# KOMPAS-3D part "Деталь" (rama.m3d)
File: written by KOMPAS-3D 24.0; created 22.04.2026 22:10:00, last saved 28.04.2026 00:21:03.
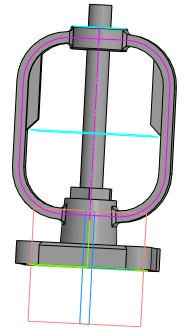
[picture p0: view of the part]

Document properties: Автор: mrdid; Полное имя файла: C:\Работа\ГОТОВЫЕ ИСХОДНИКИ\VSO2130M-F-S Клапан запорный сальниковый DN.ru Ду15-100 Ру40\исходные материалы\DN20\rama.m3d

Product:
- Part/product: Деталь
    Масса: 0.512593

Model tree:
1. Эскиз:2  (with: Ребро.Элемент выдавливания:14)
2. Элемент выдавливания:1
     Расстояние 1 = 10
3. Эскиз:3  (with: Грань.Элемент выдавливания:1, Ребро.Элемент выдавливания:1)
4. Элемент выдавливания:2
     Расстояние 2 = 10
5. Эскиз:4  (with: Грань.Элемент выдавливания:1)
6. Элемент выдавливания:3
     Угол 1 = -3
7. Эскиз:5  (with: Грань.Элемент выдавливания:3, Ребро.Элемент выдавливания:3)
8. Элемент выдавливания:4
9. Эскиз:23  (with: Грань.Элемент выдавливания:4, Ребро.Элемент выдавливания:4)
10. Элемент выдавливания:21  (labels: Деталь2; Грань.Твердое тело1)
     Расстояние 1 = 80.9875
11. Эскиз:7  (with: Грань.Элемент выдавливания:4, Ребро.Элемент выдавливания:3)
12. Элемент выдавливания:6  (with: Грань.Элемент выдавливания:3)
     Расстояние 2 = 5
13. Смещенная плоскость:4  (labels: Деталь2; Грань.Твердое тело1)
     Расстояние = 10
14. Эскиз:24  (with: Ребро.Элемент выдавливания:3)
15. Элемент выдавливания:22
     Расстояние 2 = 10
16. Эскиз:25  (with: Ребро.Элемент выдавливания:3)
17. Эскиз:26  (with: Ребро.Элемент выдавливания:3)
18. Элемент по траектории:1
     Длина траектории = 251.639
19. Скругление:8  (with: Ребро.Элемент по траектории:1)
     Радиус = 2
20. Скругление:9  (with: Ребро.Элемент по траектории:1)
     Радиус = 2
21. Смещенная плоскость:5  (with: Грань.Элемент выдавливания:1)
22. Эскиз:27  (with: Вершина.Элемент по траектории:1)
23. Элемент выдавливания:23  (with: Грань.Элемент выдавливания:22)
     Расстояние 1 = 33.7375; Смещение 1 = -3
24. Скругление:1  (with: Ребро.Элемент выдавливания:1)
     Радиус = 1.5
25. Скругление:10  (with: Ребро.Элемент выдавливания:22)
     Радиус = 0.5
26. Фаска:1  (with: Ребро.Элемент выдавливания:23)
     Угол = 45; Длина 1 = 5; Длина 2 = 5
27. Массив по концентрической сетке:1  (with: Элемент выдавливания:2, Эскиз:3)  (labels: Клапан запорный DN.ru Ду20 Ру40)  (4 pattern instances)
     Шаг 2 = 360

Expressions: DN/2; DN/4; H/4
Referenced files in C:\Работа\ГОТОВЫЕ ИСХОДНИКИ\VSO2130M-F-S Клапан запорный сальниковый DN.ru Ду15-100 Ру40\исходные материалы\DN20\: VSO2130M-F-S Клапан запорный DN.ru Ду20 Ру40.a3d
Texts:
  DN+5
  Ось Y.Начало координат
